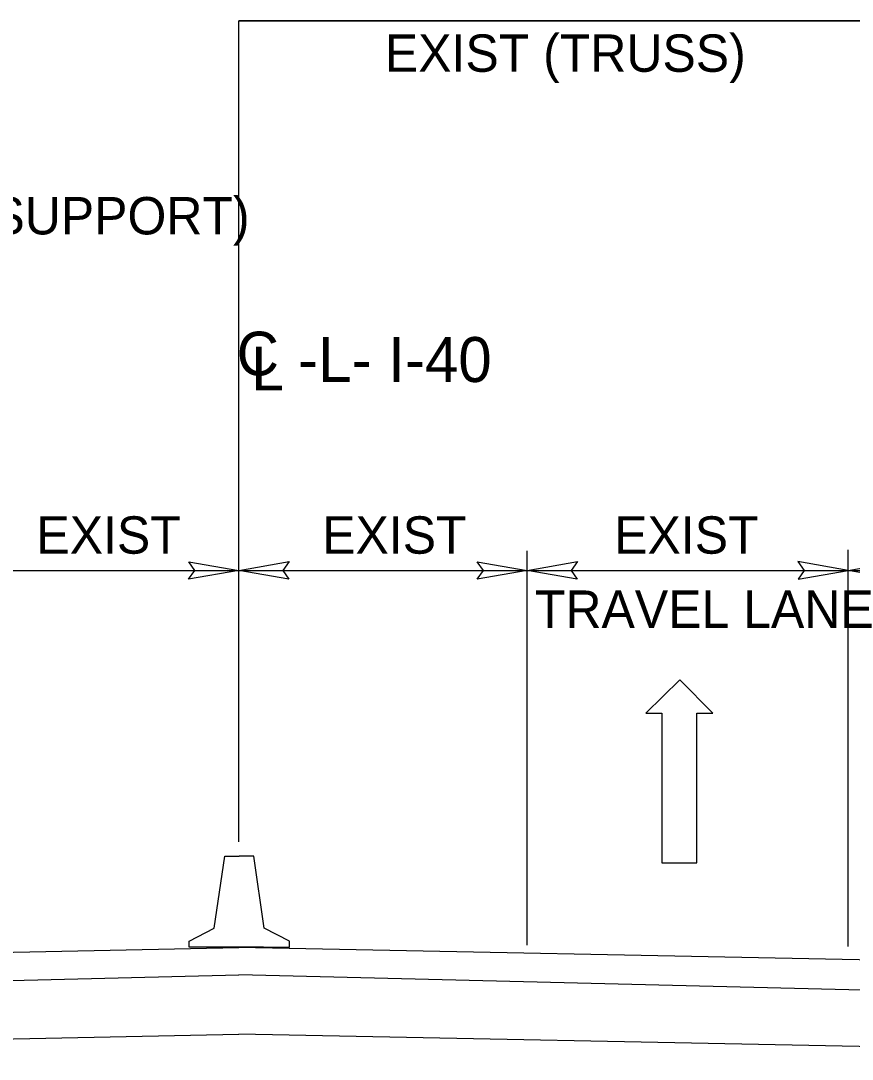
# Model space of a CAD drawing. Extents: x 1726790 to 1728895, y 539219 to 541550.
# Drawn here: x 1727429.16 to 1727460.34, y 539506.17 to 539545.09 of the extents above; entities that cross this region are included whole.
import ezdxf

# ---------------------------------------------------------------- set-up
doc = ezdxf.new("R2010")
doc.units = 0
for name, color, linetype in [('Default', 7, 'Continuous'), ('Scratch_Level_0', 7, 'Continuous'), ('Typical Pavement Slope CELL', 7, 'Continuous'), ('Typical Pavement Slope Information CELL', 7, 'Continuous'), ('Typical Text Centerline CELL', 7, 'Continuous')]:
    doc.layers.add(name, color=color, linetype=linetype)

msp = doc.modelspace()

# ---------------------------------------------------------------- linework, layer by layer
at = {"layer": 'Default'}
for p, q in [((1727437.334, 539514.314), (1727437.334, 539545.095)), ((1727463.544, 539545.095), (1727437.334, 539545.095)), ((1727448.153, 539510.44), (1727448.153, 539525.232)), ((1727460.183, 539510.396), (1727460.183, 539525.263)), ((1727426.534, 539524.493), (1727437.334, 539524.493)), ((1727437.334, 539524.493), (1727448.174, 539524.493)), ((1727448.174, 539524.493), (1727460.183, 539524.493)), ((1727460.183, 539524.493), (1727472.192, 539524.493)), ((1727453.874, 539520.397), (1727452.594, 539519.137)), ((1727455.114, 539519.137), (1727453.874, 539520.397)), ((1727452.594, 539519.137), (1727453.194, 539519.137)), ((1727453.194, 539519.137), (1727453.194, 539513.537)), ((1727454.514, 539513.537), (1727454.514, 539519.137)), ((1727454.514, 539519.137), (1727455.114, 539519.137)), ((1727453.194, 539513.537), (1727454.514, 539513.537))]:
    msp.add_line(p, q, dxfattribs=at)
for points in [[(1727435.458, 539524.816), (1727437.334, 539524.493), (1727435.448, 539524.16), (1727435.687, 539524.493)], [(1727439.209, 539524.17), (1727437.334, 539524.493), (1727439.22, 539524.826), (1727438.98, 539524.493)], [(1727446.277, 539524.816), (1727448.153, 539524.493), (1727446.267, 539524.159), (1727446.506, 539524.493)], [(1727450.028, 539524.17), (1727448.153, 539524.493), (1727450.039, 539524.826), (1727449.799, 539524.493)], [(1727458.308, 539524.17), (1727460.183, 539524.493), (1727458.297, 539524.826), (1727458.537, 539524.493)], [(1727462.059, 539524.17), (1727460.183, 539524.493), (1727462.069, 539524.826), (1727461.83, 539524.493)]]:
    msp.add_lwpolyline(points, close=True, dxfattribs=at)
at = {"layer": 'Scratch_Level_0'}
msp.add_line((1727437.334, 539545.095), (1727460.834, 539545.095), dxfattribs=at)
at = {"layer": 'Typical Pavement Slope CELL'}
for p, q in [((1727436.417, 539511.079), (1727436.811, 539513.782)), ((1727436.811, 539513.782), (1727437.354, 539513.782)), ((1727437.898, 539513.782), (1727437.354, 539513.782)), ((1727438.292, 539511.079), (1727437.898, 539513.782)), ((1727390.486, 539509.422), (1727437.334, 539510.358)), ((1727484.179, 539509.422), (1727437.334, 539510.358)), ((1727390.486, 539508.172), (1727437.334, 539509.336)), ((1727496.148, 539507.879), (1727437.334, 539509.336)), ((1727390.486, 539506.17), (1727437.334, 539507.107)), ((1727471.521, 539506.427), (1727437.334, 539507.111))]:
    msp.add_line(p, q, dxfattribs=at)
for points in [[(1727438.263, 539510.375), (1727435.473, 539510.375), (1727435.473, 539510.59), (1727436.417, 539511.079)], [(1727436.445, 539510.375), (1727439.236, 539510.375), (1727439.236, 539510.59), (1727438.292, 539511.079)]]:
    msp.add_lwpolyline(points, dxfattribs=at)

# ---------------------------------------------------------------- texts
at = {"layer": 'Typical Pavement Slope Information CELL'}
for s, height, p in [('EXIST (TRUSS)', 1.40103, (1727442.812, 539543.182)), ('EXIST (SUPPORT)', 1.40103, (1727421.501, 539537.087)), ('EXIST', 1.401, (1727429.745, 539525.119)), ('EXIST', 1.401, (1727440.461, 539525.119)), ('EXIST', 1.401, (1727451.41, 539525.119)), ('TRAVEL LANE', 1.40103, (1727448.437, 539522.339))]:
    msp.add_text(s, height=height, dxfattribs=at).set_placement(p)
at = {"layer": 'Typical Text Centerline CELL'}
for s, height, rotation, p in [('C', 1.64, 0.0443, (1727437.257, 539531.8)), ('-L- I-40', 1.6842, 359.9417, (1727439.558, 539531.561)), ('L', 1.641, 359.9912, (1727437.803, 539531.24))]:
    msp.add_text(s, height=height, rotation=rotation, dxfattribs=at).set_placement(p)

doc.saveas('drawing.dxf')
